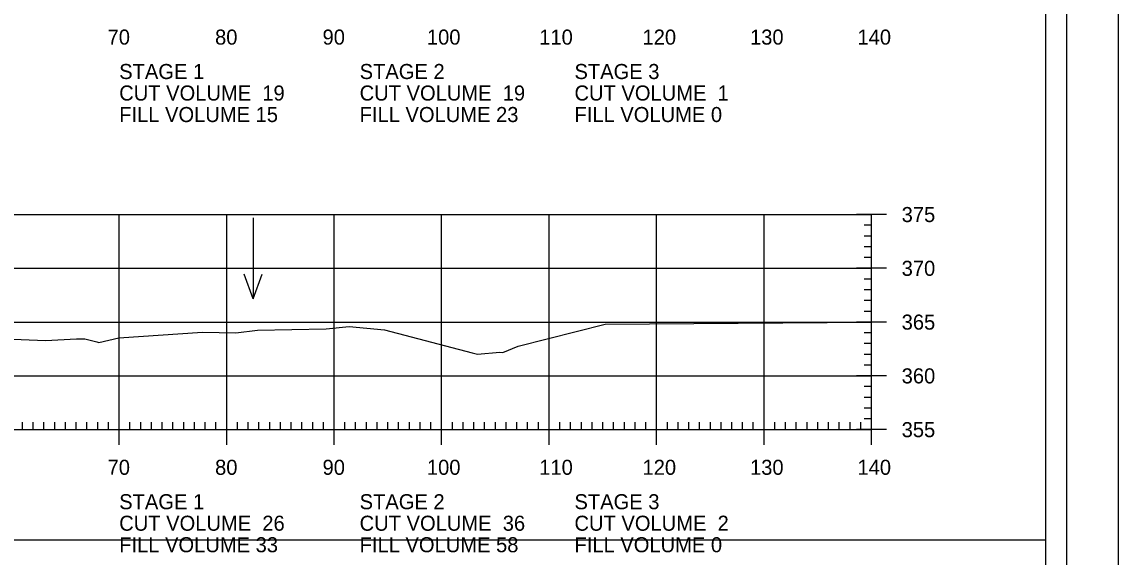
# Model space of a CAD drawing. Extents: x 1368910 to 1369601, y 380116 to 380950.
# Drawn here: x 1369141.2 to 1369243.2, y 380630.9 to 380680.7 of the extents above; entities that cross this region are included whole.
import ezdxf

# ---------------------------------------------------------------- set-up
doc = ezdxf.new("R2010")
doc.units = 0
for name, color, linetype in [('R_Axis', 7, 'Continuous'), ('R_Axis Annot', 7, 'Continuous'), ('R_Border', 7, 'Continuous'), ('R_Exist Surface', 7, 'Continuous'), ('R_Grid', 7, 'Continuous'), ('R_No Plot', 7, 'Continuous'), ('R_Water Annot', 7, 'Continuous')]:
    doc.layers.add(name, color=color, linetype=linetype)

msp = doc.modelspace()

# ---------------------------------------------------------------- linework, layer by layer
at = {"layer": 'R_Axis'}
for p, q in [((1369221.64, 380662.76), (1369218.84, 380662.76)), ((1369220.24, 380642.76), (1369220.24, 380662.76)), ((1369220.24, 380661.76), (1369219.54, 380661.76)), ((1369220.24, 380660.76), (1369219.54, 380660.76)), ((1369220.24, 380659.76), (1369219.54, 380659.76)), ((1369220.24, 380658.76), (1369219.54, 380658.76)), ((1369221.64, 380657.76), (1369218.84, 380657.76)), ((1369220.24, 380656.76), (1369219.54, 380656.76)), ((1369220.24, 380655.76), (1369219.54, 380655.76)), ((1369220.24, 380654.76), (1369219.54, 380654.76)), ((1369220.24, 380653.76), (1369219.54, 380653.76)), ((1369221.64, 380652.76), (1369218.84, 380652.76)), ((1369220.24, 380651.76), (1369219.54, 380651.76)), ((1369220.24, 380650.76), (1369219.54, 380650.76)), ((1369220.24, 380649.76), (1369219.54, 380649.76)), ((1369220.24, 380648.76), (1369219.54, 380648.76)), ((1369221.64, 380647.76), (1369218.84, 380647.76)), ((1369220.24, 380646.76), (1369219.54, 380646.76)), ((1369220.24, 380645.76), (1369219.54, 380645.76)), ((1369220.24, 380644.76), (1369219.54, 380644.76)), ((1369141.24, 380642.76), (1369141.24, 380643.46)), ((1369142.24, 380642.76), (1369142.24, 380643.46)), ((1369143.24, 380642.76), (1369143.24, 380643.46)), ((1369144.24, 380642.76), (1369144.24, 380643.46)), ((1369145.24, 380642.76), (1369145.24, 380643.46)), ((1369146.24, 380642.76), (1369146.24, 380643.46)), ((1369147.24, 380642.76), (1369147.24, 380643.46)), ((1369148.24, 380642.76), (1369148.24, 380643.46)), ((1369149.24, 380642.76), (1369149.24, 380643.46)), ((1369150.24, 380641.36), (1369150.24, 380644.16)), ((1369151.24, 380642.76), (1369151.24, 380643.46)), ((1369152.24, 380642.76), (1369152.24, 380643.46)), ((1369153.24, 380642.76), (1369153.24, 380643.46)), ((1369154.24, 380642.76), (1369154.24, 380643.46)), ((1369155.24, 380642.76), (1369155.24, 380643.46)), ((1369156.24, 380642.76), (1369156.24, 380643.46)), ((1369157.24, 380642.76), (1369157.24, 380643.46)), ((1369158.24, 380642.76), (1369158.24, 380643.46)), ((1369159.24, 380642.76), (1369159.24, 380643.46)), ((1369160.24, 380641.36), (1369160.24, 380644.16)), ((1369161.24, 380642.76), (1369161.24, 380643.46)), ((1369162.24, 380642.76), (1369162.24, 380643.46)), ((1369163.24, 380642.76), (1369163.24, 380643.46)), ((1369164.24, 380642.76), (1369164.24, 380643.46)), ((1369165.24, 380642.76), (1369165.24, 380643.46)), ((1369166.24, 380642.76), (1369166.24, 380643.46)), ((1369167.24, 380642.76), (1369167.24, 380643.46)), ((1369168.24, 380642.76), (1369168.24, 380643.46)), ((1369169.24, 380642.76), (1369169.24, 380643.46)), ((1369170.24, 380641.36), (1369170.24, 380644.16)), ((1369171.24, 380642.76), (1369171.24, 380643.46)), ((1369172.24, 380642.76), (1369172.24, 380643.46)), ((1369173.24, 380642.76), (1369173.24, 380643.46)), ((1369174.24, 380642.76), (1369174.24, 380643.46)), ((1369175.24, 380642.76), (1369175.24, 380643.46)), ((1369176.24, 380642.76), (1369176.24, 380643.46)), ((1369177.24, 380642.76), (1369177.24, 380643.46)), ((1369178.24, 380642.76), (1369178.24, 380643.46)), ((1369179.24, 380642.76), (1369179.24, 380643.46)), ((1369180.24, 380641.36), (1369180.24, 380644.16)), ((1369181.24, 380642.76), (1369181.24, 380643.46)), ((1369182.24, 380642.76), (1369182.24, 380643.46)), ((1369183.24, 380642.76), (1369183.24, 380643.46)), ((1369184.24, 380642.76), (1369184.24, 380643.46)), ((1369185.24, 380642.76), (1369185.24, 380643.46)), ((1369186.24, 380642.76), (1369186.24, 380643.46)), ((1369187.24, 380642.76), (1369187.24, 380643.46)), ((1369188.24, 380642.76), (1369188.24, 380643.46)), ((1369189.24, 380642.76), (1369189.24, 380643.46)), ((1369190.24, 380641.36), (1369190.24, 380644.16)), ((1369191.24, 380642.76), (1369191.24, 380643.46)), ((1369192.24, 380642.76), (1369192.24, 380643.46)), ((1369193.24, 380642.76), (1369193.24, 380643.46)), ((1369194.24, 380642.76), (1369194.24, 380643.46)), ((1369195.24, 380642.76), (1369195.24, 380643.46)), ((1369196.24, 380642.76), (1369196.24, 380643.46)), ((1369197.24, 380642.76), (1369197.24, 380643.46)), ((1369198.24, 380642.76), (1369198.24, 380643.46)), ((1369199.24, 380642.76), (1369199.24, 380643.46)), ((1369200.24, 380641.36), (1369200.24, 380644.16)), ((1369201.24, 380642.76), (1369201.24, 380643.46)), ((1369202.24, 380642.76), (1369202.24, 380643.46)), ((1369203.24, 380642.76), (1369203.24, 380643.46)), ((1369204.24, 380642.76), (1369204.24, 380643.46)), ((1369205.24, 380642.76), (1369205.24, 380643.46)), ((1369206.24, 380642.76), (1369206.24, 380643.46)), ((1369207.24, 380642.76), (1369207.24, 380643.46)), ((1369208.24, 380642.76), (1369208.24, 380643.46)), ((1369209.24, 380642.76), (1369209.24, 380643.46)), ((1369210.24, 380641.36), (1369210.24, 380644.16)), ((1369211.24, 380642.76), (1369211.24, 380643.46)), ((1369212.24, 380642.76), (1369212.24, 380643.46)), ((1369213.24, 380642.76), (1369213.24, 380643.46)), ((1369214.24, 380642.76), (1369214.24, 380643.46)), ((1369215.24, 380642.76), (1369215.24, 380643.46)), ((1369216.24, 380642.76), (1369216.24, 380643.46)), ((1369217.24, 380642.76), (1369217.24, 380643.46)), ((1369218.24, 380642.76), (1369218.24, 380643.46)), ((1369219.24, 380642.76), (1369219.24, 380643.46)), ((1369220.24, 380643.76), (1369219.54, 380643.76)), ((1369220.24, 380641.36), (1369220.24, 380644.16)), ((1368940.24, 380642.76), (1369220.24, 380642.76)), ((1369221.64, 380642.76), (1369218.84, 380642.76))]:
    msp.add_line(p, q, dxfattribs=at)
at = {"layer": 'R_Border'}
msp.add_line((1369238.42, 380527.76), (1369238.42, 380733.22), dxfattribs=at)
at = {"layer": 'R_Exist Surface'}
msp.add_lwpolyline([(1369135.8, 380651.36), (1369143.39, 380651.06), (1369146.27, 380651.22), (1369147.04, 380651.19), (1369148.16, 380650.94), (1369148.33, 380650.86), (1369150.2, 380651.29), (1369158, 380651.81), (1369161.1, 380651.77), (1369163.11, 380652), (1369169.51, 380652.12), (1369171.65, 380652.34), (1369174.92, 380652.03), (1369183.09, 380649.9), (1369183.57, 380649.79), (1369185.64, 380649.95), (1369185.94, 380649.93), (1369187.36, 380650.51), (1369195.45, 380652.57), (1369220.24, 380652.76)], dxfattribs=at)
at = {"layer": 'R_Grid'}
for p, q in [((1368940.24, 380662.76), (1369220.24, 380662.76)), ((1369150.24, 380642.76), (1369150.24, 380662.76)), ((1369160.24, 380642.76), (1369160.24, 380662.76)), ((1369170.24, 380642.76), (1369170.24, 380662.76)), ((1369180.24, 380642.76), (1369180.24, 380662.76)), ((1369190.24, 380642.76), (1369190.24, 380662.76)), ((1369200.24, 380642.76), (1369200.24, 380662.76)), ((1369210.24, 380642.76), (1369210.24, 380662.76)), ((1369220.24, 380642.76), (1369220.24, 380662.76)), ((1368940.24, 380657.76), (1369220.24, 380657.76)), ((1368940.24, 380652.76), (1369220.24, 380652.76)), ((1368940.24, 380647.76), (1369220.24, 380647.76)), ((1368940.24, 380642.76), (1369220.24, 380642.76))]:
    msp.add_line(p, q, dxfattribs=at)
at = {"layer": 'R_No Plot'}
for points in [[(1368909.84, 380737.11), (1369243.18, 380737.11), (1369243.18, 380523.78), (1368909.84, 380523.78)], [(1369236.42, 380632.49), (1368924.24, 380632.49), (1368924.24, 380731.22), (1369173.78, 380731.22), (1369173.78, 380721.34), (1369191.32, 380721.34), (1369215.42, 380721.34), (1369215.42, 380699.01), (1369236.42, 380699.01)], [(1368924.24, 380731.22), (1369173.78, 380731.22), (1369173.78, 380721.34), (1369191.32, 380721.34), (1369215.42, 380721.34), (1369215.42, 380699.01), (1369236.42, 380699.01), (1369236.42, 380529.76), (1368924.24, 380529.76)]]:
    msp.add_lwpolyline(points, close=True, dxfattribs=at)
at = {"layer": 'R_Water Annot'}
for p, q in [((1369162.7, 380662.46), (1369162.7, 380654.92)), ((1369162.7, 380654.92), (1369161.86, 380657.23)), ((1369162.7, 380654.92), (1369163.54, 380657.23))]:
    msp.add_line(p, q, dxfattribs=at)

# ---------------------------------------------------------------- texts
at = {"layer": 'R_Axis Annot'}
for s, p in [('70', (1369149.16, 380678.56)), ('80', (1369159.16, 380678.56)), ('90', (1369169.16, 380678.56)), ('100', (1369178.87, 380678.56)), ('110', (1369189.32, 380678.56)), ('120', (1369198.93, 380678.56)), ('130', (1369208.93, 380678.56)), ('140', (1369218.93, 380678.56)), ('STAGE 1', (1369150.24, 380675.36)), ('STAGE 2', (1369172.61, 380675.36)), ('STAGE 3', (1369192.6, 380675.36)), ('CUT VOLUME  19', (1369150.24, 380673.36)), ('CUT VOLUME  19', (1369172.61, 380673.36)), ('CUT VOLUME  1', (1369192.6, 380673.36)), ('FILL VOLUME 15', (1369150.24, 380671.36)), ('FILL VOLUME 23', (1369172.61, 380671.36)), ('FILL VOLUME 0', (1369192.6, 380671.36)), ('375', (1369223.04, 380662.06)), ('370', (1369223.04, 380657.06)), ('365', (1369223.04, 380652.06)), ('360', (1369223.04, 380647.06)), ('355', (1369223.04, 380642.06)), ('70', (1369149.16, 380638.56)), ('80', (1369159.16, 380638.56)), ('90', (1369169.16, 380638.56)), ('100', (1369178.87, 380638.56)), ('110', (1369189.32, 380638.56)), ('120', (1369198.93, 380638.56)), ('130', (1369208.93, 380638.56)), ('140', (1369218.93, 380638.56)), ('STAGE 1', (1369150.24, 380635.36)), ('STAGE 2', (1369172.61, 380635.36)), ('STAGE 3', (1369192.6, 380635.36)), ('CUT VOLUME  26', (1369150.24, 380633.36)), ('CUT VOLUME  36', (1369172.61, 380633.36)), ('CUT VOLUME  2', (1369192.6, 380633.36)), ('FILL VOLUME 33', (1369150.24, 380631.36)), ('FILL VOLUME 58', (1369172.61, 380631.36)), ('FILL VOLUME 0', (1369192.6, 380631.36))]:
    msp.add_text(s, height=1.4, dxfattribs=at).set_placement(p)

doc.saveas('drawing.dxf')
